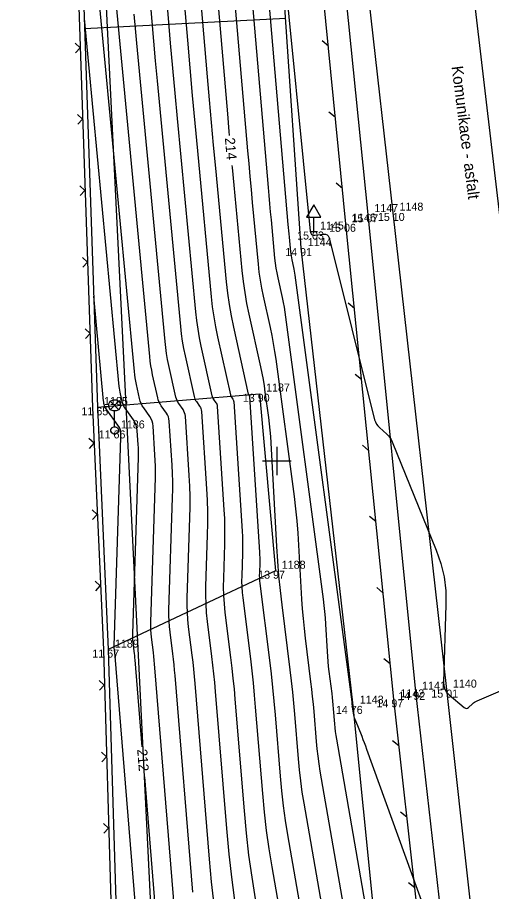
# Model space of a CAD drawing. Extents: x -711234 to -710007, y -1026313 to -1025448.
# Drawn here: x -710934.08 to -710917.49, y -1025815.07 to -1025784.48 of the extents above; entities that cross this region are included whole.
import ezdxf

# ---------------------------------------------------------------- set-up
doc = ezdxf.new("R2010")
doc.units = 0
for name, color, linetype in [('Ex_Contour Labels', 7, 'Continuous'), ('Ex_Major Contours', 7, 'Continuous'), ('Ex_Minor Contours', 7, 'Continuous'), ('Z_body', 7, 'Continuous'), ('Z_body_cisla', 7, 'Continuous'), ('Z_body_vysky_redukovane', 7, 'Continuous'), ('Z_dopravni_znacky', 7, 'Continuous'), ('Z_hektometricka_sit', 7, 'Continuous'), ('Z_hrany_paty', 7, 'Continuous'), ('Z_katastr_hranice', 7, 'Continuous'), ('Z_komunikace', 7, 'Continuous'), ('Z_ploty', 7, 'Continuous'), ('Z_ploty_znacky', 7, 'Continuous'), ('Z_popisy', 7, 'Continuous'), ('Z_site_vo_znaky', 7, 'Continuous'), ('Z_svodidla', 7, 'Continuous'), ('Z_svodidla_znacky', 7, 'Continuous'), ('Z_technicke_srafy', 7, 'Continuous'), ('Z_vdz12_plna', 7, 'Continuous'), ('Z_vdz25_plna', 7, 'Continuous'), ('Z_zelen_obvod', 7, 'Continuous')]:
    doc.layers.add(name, color=color, linetype=linetype)

# ---------------------------------------------------------------- blocks, each defined once
blk = doc.blocks.new('POINT_DISPLAY')
blk.add_line((0, 0), (0, 0))
blk = doc.blocks.new('Z34')
for p, q in [((-0.2, 0.93), (-0.15, 1.02)), ((-0.2, 0.82), (-0.2, 0.93)), ((-0.15, 1.02), (-0.05, 1.07)), ((0.15, 0.72), (-0.15, 1.02)), ((0.15, 1.02), (-0.15, 0.72)), ((-0.05, 1.07), (0.05, 1.07)), ((0.05, 1.07), (0.15, 1.02)), ((0.15, 1.02), (0.2, 0.93)), ((0.2, 0.93), (0.2, 0.82)), ((-0.15, 0.72), (-0.2, 0.82)), ((-0.05, 0.68), (-0.15, 0.72)), ((0.05, 0.68), (-0.05, 0.68)), ((0, 0.13), (0, 0.68)), ((0.15, 0.72), (0.05, 0.68)), ((0.2, 0.82), (0.15, 0.72)), ((-0.13, 0.03), (-0.1, 0.08)), ((-0.13, -0.03), (-0.13, 0.03)), ((-0.1, 0.08), (-0.08, 0.1)), ((-0.08, 0.1), (-0.03, 0.13)), ((-0.03, 0.13), (0.03, 0.13)), ((0.03, 0.13), (0.08, 0.1)), ((0.08, 0.1), (0.1, 0.08)), ((0.1, 0.08), (0.13, 0.03)), ((0.13, 0.03), (0.13, -0.03)), ((-0.1, -0.08), (-0.13, -0.03)), ((-0.08, -0.1), (-0.1, -0.08)), ((-0.03, -0.13), (-0.08, -0.1)), ((0.03, -0.13), (-0.03, -0.13)), ((0.08, -0.1), (0.03, -0.13)), ((0.1, -0.08), (0.08, -0.1)), ((0.13, -0.03), (0.1, -0.08))]:
    blk.add_line(p, q)
blk = doc.blocks.new('Z212')
for p, q in [((-0.17, 0.17), (0, 0)), ((0, 0), (0.17, 0.17))]:
    blk.add_line(p, q)
blk = doc.blocks.new('Z529')
blk.add_line((0, 0), (0.2, 0.2))
blk = doc.blocks.new('Z527')
for p, q in [((0, 0.93), (-0.25, 0.5)), ((0.25, 0.5), (0, 0.93)), ((-0.25, 0.5), (0.25, 0.5)), ((0, 0), (0, 0.5)), ((-0.13, 0), (0.13, 0))]:
    blk.add_line(p, q)

msp = doc.modelspace()

# ---------------------------------------------------------------- linework, layer by layer
at = {"layer": 'Ex_Major Contours'}
for points in [[(-710926.655, -1025788.609), (-710926.667, -1025788.476), (-710926.721, -1025787.851), (-710927.558, -1025778.102)], [(-710924.825, -1025781.985), (-710923.835, -1025791.963), (-710923.819, -1025792.028), (-710923.786, -1025792.072), (-710923.736, -1025792.095), (-710923.669, -1025792.096), (-710923.366, -1025792.059), (-710923.297, -1025792.06), (-710923.243, -1025792.082), (-710923.203, -1025792.124), (-710923.177, -1025792.188), (-710921.581, -1025798.556), (-710921.555, -1025798.634), (-710921.518, -1025798.707), (-710921.471, -1025798.773), (-710921.413, -1025798.832), (-710921.158, -1025799.056), (-710921.098, -1025799.115), (-710921.047, -1025799.179), (-710921.003, -1025799.249), (-710920.967, -1025799.325), (-710919.426, -1025803.118), (-710919.264, -1025803.583), (-710919.153, -1025804.057), (-710919.093, -1025804.539), (-710919.084, -1025805.031), (-710919.171, -1025807.744), (-710919.163, -1025807.871), (-710919.127, -1025807.985), (-710919.066, -1025808.088), (-710918.978, -1025808.179), (-710918.444, -1025808.628), (-710918.407, -1025808.651), (-710918.371, -1025808.658), (-710918.335, -1025808.65), (-710918.299, -1025808.625), (-710918.156, -1025808.495), (-710918.12, -1025808.464), (-710918.081, -1025808.437), (-710918.04, -1025808.413), (-710917.996, -1025808.392), (-710912.016, -1025805.822)], [(-710929.44, -1025783.934), (-710929.38, -1025784.624), (-710929.319, -1025785.313), (-710929.256, -1025786.003), (-710929.191, -1025786.692), (-710928.376, -1025795.297), (-710928.348, -1025795.555), (-710928.312, -1025795.811), (-710928.267, -1025796.066), (-710928.215, -1025796.32), (-710927.9, -1025797.74), (-710927.887, -1025797.788), (-710927.869, -1025797.834), (-710927.847, -1025797.878), (-710927.82, -1025797.92), (-710927.705, -1025798.083), (-710927.679, -1025798.125), (-710927.66, -1025798.169), (-710927.647, -1025798.215), (-710927.641, -1025798.264), (-710927.466, -1025800.973), (-710927.445, -1025801.376), (-710927.434, -1025801.779), (-710927.432, -1025802.182), (-710927.44, -1025802.585), (-710927.498, -1025804.389), (-710927.501, -1025804.696), (-710927.493, -1025805.003), (-710927.473, -1025805.309), (-710927.441, -1025805.615), (-710927.288, -1025806.837), (-710927.251, -1025807.143), (-710927.218, -1025807.449), (-710927.188, -1025807.755), (-710927.161, -1025808.062), (-710926.77, -1025812.856), (-710926.686, -1025813.756), (-710926.582, -1025814.654), (-710926.458, -1025815.549)], [(-710931.747, -1025784.512), (-710930.527, -1025797.388), (-710930.52, -1025797.455), (-710930.51, -1025797.521), (-710930.499, -1025797.587), (-710930.485, -1025797.653), (-710930.427, -1025797.916), (-710930.41, -1025797.98), (-710930.386, -1025798.042), (-710930.356, -1025798.1), (-710930.32, -1025798.157), (-710930.032, -1025798.564), (-710929.978, -1025798.652), (-710929.938, -1025798.745), (-710929.91, -1025798.843), (-710929.897, -1025798.946), (-710929.866, -1025799.423), (-710929.86, -1025799.538), (-710929.857, -1025799.653), (-710929.856, -1025799.768), (-710929.859, -1025799.882), (-710930.056, -1025806.051), (-710930.057, -1025806.128), (-710930.055, -1025806.204), (-710930.05, -1025806.28), (-710930.042, -1025806.356), (-710930.004, -1025806.659), (-710929.995, -1025806.735), (-710929.986, -1025806.811), (-710929.979, -1025806.887), (-710929.972, -1025806.963), (-710929.724, -1025810.006)], [(-710922.092, -1025823.253), (-710924.05, -1025811.969), (-710924.112, -1025811.584), (-710924.166, -1025811.197), (-710924.211, -1025810.81), (-710924.247, -1025810.421), (-710924.374, -1025808.864), (-710924.408, -1025808.475), (-710924.446, -1025808.086), (-710924.488, -1025807.698), (-710924.535, -1025807.31), (-710924.819, -1025805.036), (-710924.879, -1025804.527), (-710924.929, -1025804.018), (-710924.971, -1025803.508), (-710925.003, -1025802.997), (-710925.204, -1025799.367), (-710925.218, -1025799.143), (-710925.237, -1025798.921), (-710925.26, -1025798.698), (-710925.288, -1025798.476), (-710925.406, -1025797.589), (-710925.438, -1025797.367), (-710925.475, -1025797.147), (-710925.516, -1025796.927), (-710925.562, -1025796.708), (-710925.972, -1025794.865), (-710926.05, -1025794.484), (-710926.116, -1025794.101), (-710926.171, -1025793.716), (-710926.214, -1025793.33), (-710926.496, -1025790.353), (-710926.554, -1025789.728), (-710926.561, -1025789.655)], [(-710929.638, -1025811.052), (-710929.118, -1025817.417)]]:
    msp.add_lwpolyline(points, dxfattribs=at)
at = {"layer": 'Ex_Minor Contours'}
for points in [[(-710919.388, -1025816.895), (-710921.851, -1025810.091), (-710921.892, -1025809.979), (-710921.934, -1025809.867), (-710921.977, -1025809.756), (-710922.021, -1025809.646), (-710922.253, -1025809.073), (-710922.269, -1025809.028), (-710922.284, -1025808.982), (-710922.296, -1025808.936), (-710922.305, -1025808.889), (-710922.353, -1025808.615), (-710922.354, -1025808.605), (-710922.355, -1025808.594), (-710922.357, -1025808.569), (-710922.359, -1025808.553), (-710922.363, -1025808.524), (-710922.364, -1025808.51), (-710922.365, -1025808.497), (-710922.367, -1025808.46), (-710922.368, -1025808.451), (-710922.368, -1025808.443), (-710922.369, -1025808.435), (-710922.37, -1025808.426), (-710924.363, -1025793.494), (-710924.373, -1025793.426), (-710924.384, -1025793.358), (-710924.397, -1025793.291), (-710924.411, -1025793.224), (-710924.47, -1025792.957), (-710924.484, -1025792.89), (-710924.496, -1025792.823), (-710924.505, -1025792.755), (-710924.513, -1025792.687), (-710924.562, -1025792.164), (-710924.573, -1025792.054), (-710924.583, -1025791.944), (-710924.593, -1025791.834), (-710924.602, -1025791.724), (-710925.937, -1025776.168)], [(-710926.477, -1025776.813), (-710925.309, -1025790.433), (-710925.284, -1025790.715), (-710925.259, -1025790.997), (-710925.233, -1025791.278), (-710925.207, -1025791.56), (-710925.08, -1025792.901), (-710925.061, -1025793.075), (-710925.036, -1025793.249), (-710925.006, -1025793.421), (-710924.971, -1025793.593), (-710924.819, -1025794.278), (-710924.783, -1025794.449), (-710924.75, -1025794.622), (-710924.721, -1025794.794), (-710924.696, -1025794.968), (-710923.379, -1025804.836), (-710923.353, -1025805.052), (-710923.33, -1025805.269), (-710923.312, -1025805.487), (-710923.298, -1025805.705), (-710923.245, -1025806.663), (-710923.233, -1025806.838), (-710923.219, -1025807.013), (-710923.202, -1025807.187), (-710923.182, -1025807.361), (-710923.084, -1025808.139), (-710923.068, -1025808.272), (-710923.054, -1025808.405), (-710923.041, -1025808.537), (-710923.029, -1025808.671), (-710922.986, -1025809.203), (-710922.973, -1025809.336), (-710922.958, -1025809.469), (-710922.94, -1025809.601), (-710922.918, -1025809.733), (-710921.399, -1025818.492)], [(-710921.264, -1025823.649), (-710923.484, -1025810.851), (-710923.526, -1025810.592), (-710923.562, -1025810.333), (-710923.592, -1025810.073), (-710923.616, -1025809.812), (-710923.702, -1025808.767), (-710923.725, -1025808.506), (-710923.75, -1025808.245), (-710923.778, -1025807.985), (-710923.81, -1025807.725), (-710924.001, -1025806.199), (-710924.04, -1025805.857), (-710924.074, -1025805.515), (-710924.102, -1025805.173), (-710924.124, -1025804.83), (-710924.228, -1025802.95), (-710924.256, -1025802.522), (-710924.292, -1025802.096), (-710924.336, -1025801.67), (-710924.388, -1025801.245), (-710925.029, -1025796.442), (-710925.07, -1025796.163), (-710925.116, -1025795.885), (-710925.168, -1025795.608), (-710925.226, -1025795.331), (-710925.471, -1025794.229), (-710925.528, -1025793.953), (-710925.576, -1025793.675), (-710925.616, -1025793.396), (-710925.647, -1025793.116), (-710925.851, -1025790.956), (-710925.894, -1025790.503), (-710925.935, -1025790.049), (-710925.976, -1025789.596), (-710926.015, -1025789.142), (-710927.017, -1025777.458)], [(-710922.921, -1025822.858), (-710924.616, -1025813.087), (-710924.699, -1025812.575), (-710924.77, -1025812.061), (-710924.83, -1025811.546), (-710924.878, -1025811.03), (-710925.053, -1025808.886), (-710925.095, -1025808.406), (-710925.141, -1025807.927), (-710925.194, -1025807.449), (-710925.251, -1025806.971), (-710925.587, -1025804.286), (-710925.596, -1025804.195), (-710925.602, -1025804.104), (-710925.605, -1025804.012), (-710925.604, -1025803.921), (-710925.592, -1025803.555), (-710925.59, -1025803.464), (-710925.591, -1025803.372), (-710925.593, -1025803.281), (-710925.598, -1025803.19), (-710925.948, -1025797.752), (-710925.95, -1025797.744), (-710925.952, -1025797.736), (-710925.955, -1025797.729), (-710925.959, -1025797.722), (-710925.978, -1025797.695), (-710925.983, -1025797.688), (-710925.986, -1025797.681), (-710925.989, -1025797.673), (-710925.992, -1025797.665), (-710926.512, -1025795.319), (-710926.594, -1025794.925), (-710926.662, -1025794.528), (-710926.719, -1025794.13), (-710926.763, -1025793.729), (-710927.14, -1025789.749), (-710927.215, -1025788.952), (-710927.287, -1025788.155), (-710927.359, -1025787.357), (-710927.428, -1025786.56), (-710928.098, -1025778.747)], [(-710928.639, -1025779.392), (-710928.134, -1025785.269), (-710928.05, -1025786.238), (-710927.964, -1025787.208), (-710927.875, -1025788.177), (-710927.784, -1025789.146), (-710927.301, -1025794.252), (-710927.262, -1025794.605), (-710927.212, -1025794.956), (-710927.151, -1025795.305), (-710927.08, -1025795.653), (-710926.628, -1025797.69), (-710926.622, -1025797.711), (-710926.614, -1025797.732), (-710926.604, -1025797.751), (-710926.592, -1025797.77), (-710926.541, -1025797.842), (-710926.53, -1025797.861), (-710926.521, -1025797.881), (-710926.515, -1025797.901), (-710926.513, -1025797.923), (-710926.221, -1025802.451), (-710926.21, -1025802.646), (-710926.205, -1025802.841), (-710926.204, -1025803.036), (-710926.208, -1025803.232), (-710926.233, -1025804.013), (-710926.235, -1025804.208), (-710926.23, -1025804.403), (-710926.217, -1025804.598), (-710926.197, -1025804.792), (-710925.93, -1025806.926), (-710925.879, -1025807.347), (-710925.834, -1025807.768), (-710925.792, -1025808.189), (-710925.756, -1025808.611), (-710925.508, -1025811.639), (-710925.448, -1025812.283), (-710925.374, -1025812.926), (-710925.285, -1025813.566), (-710925.182, -1025814.205), (-710923.749, -1025822.463)], [(-710925.747, -1025815.323), (-710925.871, -1025814.558), (-710925.978, -1025813.79), (-710926.067, -1025813.02), (-710926.139, -1025812.247), (-710926.458, -1025808.336), (-710926.49, -1025807.972), (-710926.526, -1025807.608), (-710926.565, -1025807.245), (-710926.609, -1025806.881), (-710926.807, -1025805.298), (-710926.838, -1025805.001), (-710926.858, -1025804.703), (-710926.866, -1025804.404), (-710926.862, -1025804.105), (-710926.824, -1025802.908), (-710926.818, -1025802.609), (-710926.819, -1025802.31), (-710926.828, -1025802.011), (-710926.843, -1025801.712), (-710927.077, -1025798.093), (-710927.081, -1025798.058), (-710927.09, -1025798.025), (-710927.104, -1025797.993), (-710927.123, -1025797.963), (-710927.206, -1025797.845), (-710927.226, -1025797.815), (-710927.241, -1025797.783), (-710927.254, -1025797.75), (-710927.264, -1025797.715), (-710927.647, -1025795.986), (-710927.709, -1025795.685), (-710927.762, -1025795.383), (-710927.805, -1025795.08), (-710927.839, -1025794.775), (-710928.479, -1025788.01), (-710928.561, -1025787.135), (-710928.641, -1025786.26), (-710928.719, -1025785.385), (-710928.795, -1025784.51), (-710929.179, -1025780.037)], [(-710928.533, -1025816.254), (-710929.27, -1025807.237), (-710929.281, -1025807.104), (-710929.294, -1025806.97), (-710929.309, -1025806.837), (-710929.325, -1025806.703), (-710929.391, -1025806.17), (-710929.405, -1025806.037), (-710929.414, -1025805.904), (-710929.418, -1025805.77), (-710929.416, -1025805.636), (-710929.255, -1025800.582), (-710929.251, -1025800.383), (-710929.252, -1025800.184), (-710929.257, -1025799.985), (-710929.268, -1025799.786), (-710929.333, -1025798.776), (-710929.345, -1025798.686), (-710929.368, -1025798.601), (-710929.403, -1025798.52), (-710929.45, -1025798.443), (-710929.662, -1025798.144), (-710929.711, -1025798.068), (-710929.751, -1025797.987), (-710929.784, -1025797.903), (-710929.808, -1025797.816), (-710929.918, -1025797.32), (-710929.941, -1025797.207), (-710929.961, -1025797.094), (-710929.977, -1025796.98), (-710929.989, -1025796.865), (-710931.327, -1025782.739)], [(-710927.948, -1025815.092), (-710928.567, -1025807.512), (-710928.583, -1025807.321), (-710928.602, -1025807.13), (-710928.623, -1025806.939), (-710928.646, -1025806.748), (-710928.741, -1025805.985), (-710928.761, -1025805.794), (-710928.774, -1025805.603), (-710928.779, -1025805.412), (-710928.777, -1025805.22), (-710928.651, -1025801.283), (-710928.645, -1025800.999), (-710928.646, -1025800.716), (-710928.654, -1025800.432), (-710928.669, -1025800.149), (-710928.769, -1025798.605), (-710928.779, -1025798.529), (-710928.799, -1025798.457), (-710928.829, -1025798.388), (-710928.869, -1025798.323), (-710929.048, -1025798.069), (-710929.09, -1025798.004), (-710929.124, -1025797.936), (-710929.151, -1025797.865), (-710929.172, -1025797.791), (-710929.35, -1025796.986), (-710929.383, -1025796.827), (-710929.411, -1025796.666), (-710929.434, -1025796.505), (-710929.452, -1025796.343), (-710930.615, -1025784.056)], [(-710927.196, -1025815.519), (-710927.288, -1025814.726), (-710927.362, -1025813.93), (-710927.864, -1025807.787), (-710927.886, -1025807.538), (-710927.91, -1025807.289), (-710927.937, -1025807.041), (-710927.967, -1025806.792), (-710928.091, -1025805.8), (-710928.117, -1025805.552), (-710928.134, -1025805.303), (-710928.14, -1025805.054), (-710928.137, -1025804.804), (-710928.047, -1025801.983), (-710928.04, -1025801.615), (-710928.041, -1025801.247), (-710928.052, -1025800.879), (-710928.071, -1025800.512), (-710928.205, -1025798.435), (-710928.213, -1025798.372), (-710928.229, -1025798.313), (-710928.254, -1025798.256), (-710928.287, -1025798.203), (-710928.434, -1025797.994), (-710928.468, -1025797.941), (-710928.496, -1025797.885), (-710928.519, -1025797.827), (-710928.536, -1025797.766), (-710928.783, -1025796.653), (-710928.825, -1025796.446), (-710928.861, -1025796.239), (-710928.891, -1025796.03), (-710928.914, -1025795.82), (-710929.903, -1025785.374), (-710929.95, -1025784.87), (-710929.997, -1025784.366)], [(-710929.704, -1025818.579), (-710930.675, -1025806.688), (-710930.677, -1025806.669), (-710930.679, -1025806.651), (-710930.681, -1025806.633), (-710930.683, -1025806.614), (-710930.692, -1025806.541), (-710930.694, -1025806.522), (-710930.695, -1025806.504), (-710930.696, -1025806.485), (-710930.695, -1025806.467), (-710930.463, -1025799.182), (-710930.462, -1025799.152), (-710930.462, -1025799.121), (-710930.463, -1025799.091), (-710930.465, -1025799.061), (-710930.472, -1025798.939), (-710930.476, -1025798.91), (-710930.484, -1025798.881), (-710930.496, -1025798.854), (-710930.511, -1025798.829), (-710931.006, -1025798.13), (-710931.016, -1025798.114), (-710931.025, -1025798.098), (-710931.031, -1025798.08), (-710931.036, -1025798.062), (-710931.053, -1025797.987), (-710931.057, -1025797.968), (-710931.06, -1025797.949), (-710931.063, -1025797.93), (-710931.065, -1025797.911), (-710931.413, -1025794.232)]]:
    msp.add_lwpolyline(points, dxfattribs=at)
at = {"layer": 'Z_hektometricka_sit'}
for p, q in [((-710925, -1025799.5), (-710925, -1025800.5)), ((-710925.5, -1025800), (-710924.5, -1025800))]:
    msp.add_line(p, q, dxfattribs=at)
at = {"layer": 'Z_hrany_paty'}
for p, q in [((-710924.15, -1025792.55), (-710925.31, -1025775.42)), ((-710922.33, -1025808.57), (-710924.15, -1025792.55)), ((-710920.8, -1025823.87), (-710922.33, -1025808.57))]:
    msp.add_line(p, q, dxfattribs=at)
at = {"layer": 'Z_katastr_hranice'}
msp.add_lwpolyline([(-710937.26, -1025842.82), (-710936.45, -1025842.11), (-710935.96, -1025842), (-710933.08, -1025840.66), (-710931.05, -1025838.78), (-710930.88, -1025838.46), (-710929.59, -1025835.96), (-710928.58, -1025832.31), (-710932.7, -1025748.89), (-710932.82, -1025746.51)], dxfattribs=at)
at = {"layer": 'Z_komunikace'}
for p, q in [((-710921.81, -1025791.37), (-710923.4, -1025775.53)), ((-710920.14, -1025808.08), (-710921.81, -1025791.37)), ((-710918.75, -1025820.24), (-710920.14, -1025808.08))]:
    msp.add_line(p, q, dxfattribs=at)
at = {"layer": 'Z_ploty'}
for p, q in [((-710932.01, -1025781.8), (-710931.45, -1025798.13)), ((-710931.84, -1025781.79), (-710931.28, -1025798.12)), ((-710931.45, -1025798.13), (-710931.07, -1025806.61)), ((-710931.28, -1025798.12), (-710930.9, -1025806.6)), ((-710931.07, -1025806.61), (-710930.68, -1025820.12)), ((-710930.9, -1025806.6), (-710930.5, -1025820.16))]:
    msp.add_line(p, q, dxfattribs=at)
at = {"layer": 'Z_svodidla'}
for p, q in [((-710922.59, -1025791.7), (-710924.17, -1025775.65)), ((-710920.91, -1025808.34), (-710922.59, -1025791.7)), ((-710919.21, -1025823.64), (-710920.91, -1025808.34))]:
    msp.add_line(p, q, dxfattribs=at)
at = {"layer": 'Z_technicke_srafy'}
msp.add_line((-710924.69, -1025784.52), (-710931.73, -1025784.88), dxfattribs=at)
at = {"layer": 'Z_vdz12_plna'}
msp.add_line((-710918.45, -1025780.84), (-710916.74, -1025795.45), dxfattribs=at)
at = {"layer": 'Z_vdz25_plna'}
for p, q in [((-710920.93, -1025791.32), (-710922.73, -1025775.38)), ((-710919.06, -1025808), (-710920.93, -1025791.32)), ((-710917.71, -1025820.04), (-710919.06, -1025808))]:
    msp.add_line(p, q, dxfattribs=at)
at = {"layer": 'Z_zelen_obvod'}
for p, q in [((-710931.28, -1025798.12), (-710925.61, -1025797.65)), ((-710925.61, -1025797.65), (-710925.05, -1025803.84)), ((-710925.05, -1025803.84), (-710930.9, -1025806.6))]:
    msp.add_line(p, q, dxfattribs=at)

# ---------------------------------------------------------------- block references
at = {"layer": 'Z_body'}
for p in [(-710921.81, -1025791.37), (-710920.93, -1025791.32), (-710922.59, -1025791.7), (-710923.71, -1025791.97), (-710924.15, -1025792.55), (-710925.61, -1025797.65), (-710931.28, -1025798.12), (-710930.68, -1025798.93), (-710925.05, -1025803.84), (-710930.9, -1025806.6), (-710919.06, -1025808), (-710920.14, -1025808.08), (-710922.33, -1025808.57), (-710920.91, -1025808.34)]:
    msp.add_blockref('POINT_DISPLAY', p, dxfattribs=at)
at = {"layer": 'Z_dopravni_znacky'}
msp.add_blockref('Z527', (-710923.71, -1025791.97), dxfattribs=at)
at = {"layer": 'Z_ploty_znacky'}
for p, rotation in [((-710931.89, -1025785.54), 91.99999999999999), ((-710931.8, -1025788.04), 91.99999999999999), ((-710931.72, -1025790.54), 91.99999999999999), ((-710931.63, -1025793.04), 91.99999999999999), ((-710931.54, -1025795.54), 91.99999999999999), ((-710931.4, -1025799.38), 92.6), ((-710931.29, -1025801.87), 92.6), ((-710931.18, -1025804.37), 92.6), ((-710931.04, -1025807.85), 91.7), ((-710930.96, -1025810.35), 91.7), ((-710930.89, -1025812.85), 91.7)]:
    msp.add_blockref('Z212', p, dxfattribs=dict(at, rotation=rotation))
at = {"layer": 'Z_site_vo_znaky'}
msp.add_blockref('Z34', (-710930.68, -1025798.93), dxfattribs=at)
at = {"layer": 'Z_svodidla_znacky'}
for p, rotation in [((-710923.2, -1025785.48), 95.6), ((-710923.2, -1025785.48), 95.6), ((-710922.96, -1025787.97), 95.6), ((-710922.96, -1025787.97), 95.6), ((-710922.71, -1025790.46), 95.6), ((-710922.71, -1025790.46), 95.6), ((-710922.29, -1025794.66), 95.79999999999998), ((-710922.04, -1025797.15), 95.79999999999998), ((-710921.79, -1025799.63), 95.79999999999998), ((-710921.54, -1025802.12), 95.79999999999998), ((-710921.29, -1025804.61), 95.79999999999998), ((-710921.04, -1025807.1), 95.79999999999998), ((-710920.73, -1025809.97), 96.3), ((-710920.45, -1025812.46), 96.3), ((-710920.18, -1025814.94), 96.3)]:
    msp.add_blockref('Z529', p, dxfattribs=dict(at, rotation=rotation))

# ---------------------------------------------------------------- texts
at = {"layer": 'Ex_Contour Labels'}
for s, rotation, p in [('214', 275.1607, (-710926.823, -1025788.698)), ('212', 274.6695, (-710929.892, -1025810.093))]:
    msp.add_text(s, height=0.35, rotation=rotation, dxfattribs=at).set_placement(p)
at = {"layer": 'Z_body_cisla'}
for s, p in [('1147', (-710921.59, -1025791.29)), ('1148', (-710920.71, -1025791.24)), ('1146', (-710922.37, -1025791.62)), ('1145', (-710923.49, -1025791.9)), ('1144', (-710923.92, -1025792.48)), ('1187', (-710925.38, -1025797.57)), ('1185', (-710931.05, -1025798.04)), ('1186', (-710930.46, -1025798.86)), ('1188', (-710924.83, -1025803.77)), ('1189', (-710930.67, -1025806.53)), ('1140', (-710918.84, -1025807.93)), ('1142', (-710920.68, -1025808.27)), ('1141', (-710919.92, -1025808)), ('1143', (-710922.1, -1025808.49))]:
    msp.add_text(s, height=0.28, dxfattribs=at).set_placement(p)
at = {"layer": 'Z_body_vysky_redukovane'}
for s, p in [('15 07', (-710922.393, -1025791.65)), ('15 10', (-710921.467, -1025791.6)), ('15 06', (-710923.173, -1025791.98)), ('15 03', (-710924.293, -1025792.25)), ('14 91', (-710924.71, -1025792.83)), ('13 90', (-710926.193, -1025797.93)), ('11 65', (-710931.84, -1025798.4)), ('11 66', (-710931.24, -1025799.21)), ('13 97', (-710925.657, -1025804.12)), ('11 67', (-710931.46, -1025806.88)), ('15 01', (-710919.597, -1025808.28)), ('14 92', (-710920.747, -1025808.36)), ('14 76', (-710922.937, -1025808.85)), ('14 97', (-710921.517, -1025808.62))]:
    msp.add_text(s, height=0.28, dxfattribs=at).set_placement(p)
at = {"layer": 'Z_popisy'}
msp.add_text('Komunikace - asfalt', height=0.4, rotation=277.2, dxfattribs=at).set_placement((-710918.89, -1025786.2))

doc.saveas('drawing.dxf')
